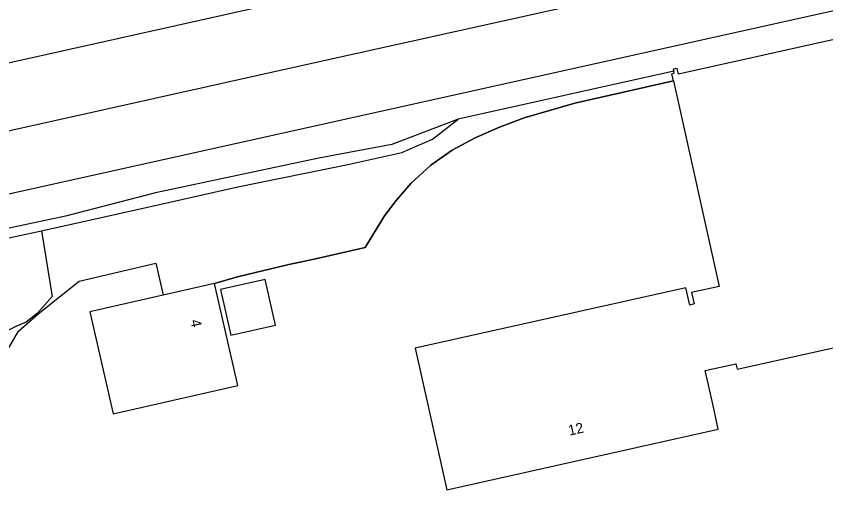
# Model space of a CAD drawing. Extents: x 161477 to 163040, y 383680 to 384868.
# Drawn here: x 161820.9 to 161899, y 383754.4 to 383800 of the extents above; entities that cross this region are included whole.
import ezdxf

# ---------------------------------------------------------------- set-up
doc = ezdxf.new("R2010")
doc.units = 0
for name, color, linetype in [('IMGEO_Grasland_overig', 7, 'Continuous'), ('IMGEO_Hek', 7, 'Continuous'), ('IMGEO_Overkapping', 7, 'Continuous'), ('IMGEO_Pand', 7, 'Continuous'), ('IMGEO_Pand_nummerreeks', 7, 'Continuous'), ('IMGEO_Spoor', 7, 'Continuous'), ('IMGEO_Spoorbaan_halfverhard', 7, 'Continuous')]:
    doc.layers.add(name, color=color, linetype=linetype)

msp = doc.modelspace()

# ---------------------------------------------------------------- linework, layer by layer
at = {"layer": 'IMGEO_Grasland_overig'}
for points in [[(161840.049, 383774.26), (161842.269, 383774.912), (161847.205, 383776.086), (161849.654, 383776.598), (161854.567, 383777.721), (161856.446, 383780.78), (161857.569, 383782.27), (161859.015, 383783.949), (161860.912, 383785.681), (161862.979, 383787.119), (161865.204, 383788.317), (161867.527, 383789.35), (161869.922, 383790.223), (161874.8, 383791.637), (161884.307, 383793.82)], [(161823.364, 383779.326), (161834.744, 383781.861), (161842.297, 383783.574), (161852.9, 383785.746), (161858.118, 383786.901), (161861.087, 383788.167), (161863.541, 383790.107)], [(161817.539, 383763.032), (161817.926, 383764.039), (161818.461, 383765.249), (161819.878, 383767.428), (161821.162, 383769.645), (161823.064, 383771.317), (161826.987, 383774.488), (161834.38, 383776.227), (161835.089, 383773.127)]]:
    msp.add_lwpolyline(points, dxfattribs=at)
at = {"layer": 'IMGEO_Hek'}
for points in [[(161884.307, 383793.82), (161874.8, 383791.637), (161869.922, 383790.223), (161867.527, 383789.35), (161865.204, 383788.317), (161862.979, 383787.119), (161860.912, 383785.681), (161859.015, 383783.949), (161857.569, 383782.27), (161856.446, 383780.78), (161854.567, 383777.721), (161849.654, 383776.598), (161847.205, 383776.086), (161842.269, 383774.912), (161840.049, 383774.26)], [(161816.906, 383761.386), (161817.539, 383763.032), (161817.926, 383764.039), (161818.461, 383765.249), (161819.878, 383767.428), (161821.162, 383769.645), (161823.064, 383771.317), (161826.987, 383774.488), (161834.38, 383776.227), (161835.055, 383773.274)]]:
    msp.add_lwpolyline(points, dxfattribs=at)
at = {"layer": 'IMGEO_Overkapping'}
msp.add_lwpolyline([(161845.927, 383770.235), (161844.94, 383774.644), (161840.624, 383773.678), (161841.612, 383769.269), (161845.927, 383770.235)], dxfattribs=at)
at = {"layer": 'IMGEO_Pand'}
for points in [[(161884.307, 383793.82), (161888.732, 383773.981), (161886.05, 383773.382), (161886.296, 383772.278), (161885.88, 383772.171), (161885.512, 383773.822), (161859.412, 383768), (161862.456, 383754.351), (161888.638, 383760.191), (161888.124, 383762.496), (161887.374, 383765.859), (161890.333, 383766.519), (161890.453, 383765.982), (162000, 383790.338), (162126.913, 383818.178), (162134.332, 383819.805), (162130.475, 383837.208), (162140.902, 383839.53), (162139.81, 383844.853)], [(162088.04, 383839.79), (162000, 383820.132), (161884.782, 383794.446), (161884.657, 383795.008), (161884.294, 383794.927), (161884.339, 383794.723)], [(161884.307, 383793.82), (161884.156, 383794.495), (161884.379, 383794.545), (161884.339, 383794.723)], [(161835.089, 383773.127), (161828.04, 383771.517), (161830.29, 383761.677), (161842.296, 383764.422), (161840.049, 383774.26)], [(161840.049, 383774.26), (161835.089, 383773.127)]]:
    msp.add_lwpolyline(points, dxfattribs=at)
at = {"layer": 'IMGEO_Spoor'}
for points in [[(161752.189, 383780.401), (161875.71, 383807.941), (162015.247, 383838.879), (162036.636, 383843.844), (162104.749, 383859.249), (162247.596, 383891.587), (162328.95, 383910.047), (162367.145, 383918.705), (162379.678, 383921.181), (162389.534, 383922.693), (162398.921, 383923.736), (162409, 383924.591)], [(161754.679, 383774.37), (161849.162, 383795.439), (161951.91, 383818.254), (162017.666, 383832.92), (162036.57, 383837.157), (162110.799, 383854.024), (162201.325, 383874.476), (162299.918, 383896.883), (162339.11, 383905.765), (162371.599, 383913.133), (162387.019, 383916.604), (162393.326, 383917.806), (162399.334, 383918.841), (162404.24, 383919.608), (162409.947, 383920.309), (162415.587, 383920.876), (162421.261, 383921.344), (162428.503, 383921.744), (162433.309, 383921.878), (162439.751, 383921.911), (162444.26, 383921.834)], [(161756.532, 383768.759), (161838.28, 383786.934), (161975.143, 383817.362), (162056.37, 383835.441), (162106.404, 383846.645), (162114.629, 383848.32), (162125.792, 383850.602), (162135.244, 383852.231), (162143.31, 383853.698), (162150.399, 383855.002), (162159.118, 383856.876), (162165.31, 383858.261), (162254.853, 383878.091), (162292.538, 383886.494), (162314.34, 383891.261), (162320.369, 383892.646), (162328.355, 383894.602), (162337.399, 383896.883)]]:
    msp.add_lwpolyline(points, dxfattribs=at)
at = {"layer": 'IMGEO_Spoorbaan_halfverhard'}
for points in [[(161884.339, 383794.723), (161863.541, 383790.107)], [(161863.541, 383790.107), (161857.156, 383787.654), (161850.119, 383786.333), (161834.375, 383782.991), (161825.676, 383780.743), (161816.733, 383778.863), (161806.838, 383776.611), (161793.135, 383773.339), (161790.49, 383772.313), (161795.562, 383773.285), (161801.935, 383774.721), (161823.364, 383779.326)], [(161823.364, 383779.326), (161824.402, 383773), (161822.963, 383771.358), (161821.905, 383770.539), (161820.899, 383770.093), (161817.974, 383768.665)]]:
    msp.add_lwpolyline(points, dxfattribs=at)

# ---------------------------------------------------------------- texts
at = {"layer": 'IMGEO_Pand_nummerreeks'}
for s, rotation, p in [('4', 282.30119, (161837.719, 383770.678)), ('12', 12.59934, (161874.278, 383759.569))]:
    msp.add_text(s, height=1, rotation=rotation, dxfattribs=at).set_placement(p)

doc.saveas('drawing.dxf')
